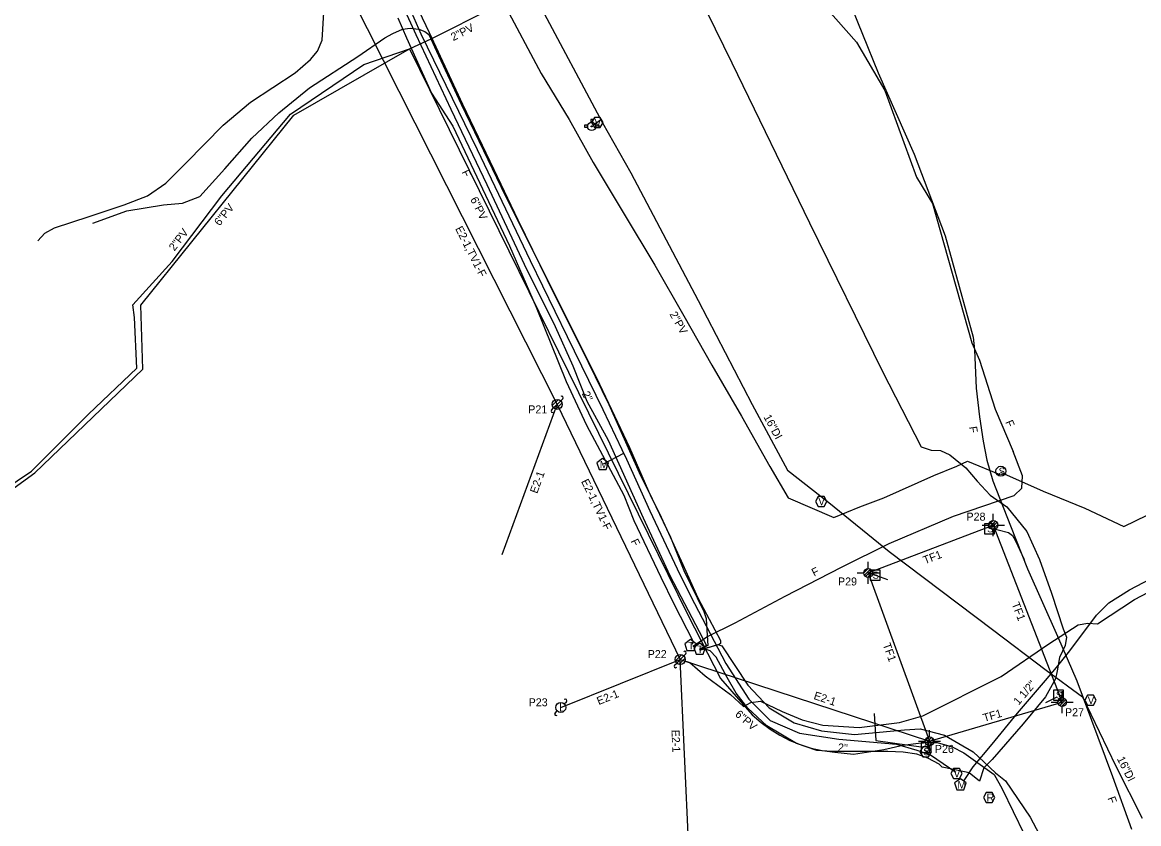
# Model space of a CAD drawing. Extents: x 1741604 to 1825760, y 1164229 to 1194908.
# Drawn here: x 1755344 to 1755902, y 1168344 to 1168745 of the extents above; entities that cross this region are included whole.
import ezdxf

# ---------------------------------------------------------------- set-up
doc = ezdxf.new("R2010")
doc.units = 0
for name, color, linetype in [('RD_EX_SU_Elec', 7, 'Continuous'), ('RD_EX_SU_H2O', 7, 'Continuous'), ('RD_EX_SU_Ovhd', 7, 'Continuous'), ('RD_EX_SU_Pole', 7, 'Continuous'), ('RD_EX_SU_Sewer', 7, 'Continuous'), ('RD_EX_SU_Telecom', 7, 'Continuous'), ('RD_EX_SU_Trfc', 7, 'Continuous'), ('RD_EX_SU_TX_H2O', 7, 'Continuous'), ('RD_EX_SU_TX_Pole', 7, 'Continuous'), ('RD_EX_SU_TX_Sewer', 7, 'Continuous'), ('RD_EX_SU_TX_Telecom', 7, 'Continuous')]:
    doc.layers.add(name, color=color, linetype=linetype)

# ---------------------------------------------------------------- blocks, each defined once
blk = doc.blocks.new('SUE_SMH')
at = {"layer": 'RD_EX_SU_Sewer'}
blk.add_circle((0, 0), 2.5, dxfattribs=at)
blk.add_text('S', height=3.57, dxfattribs=at).set_placement((-1.1, -1.79))

msp = doc.modelspace()

# ---------------------------------------------------------------- linework, layer by layer
at = {"layer": 'RD_EX_SU_Elec'}
msp.add_lwpolyline([(1755352.15, 1168636.03), (1755355.71, 1168639.76), (1755360.62, 1168642.49), (1755377.96, 1168648.25), (1755395.32, 1168654.04), (1755407.08, 1168658.47), (1755416.27, 1168664.85), (1755426.19, 1168674.91), (1755444.85, 1168693.91), (1755458.49, 1168705.44), (1755480.84, 1168720.11), (1755488.48, 1168726.7), (1755492.01, 1168730.8), (1755494.34, 1168736.34), (1755495.74, 1168758.73), (1755498.75, 1168776.84)], dxfattribs=at)
at = {"layer": 'RD_EX_SU_H2O'}
for p, q in [((1755627.04, 1168693.86), (1755625.4, 1168693.86)), ((1755625.4, 1168693.86), (1755625.4, 1168692.81)), ((1755625.4, 1168692.81), (1755627, 1168692.81)), ((1755628.57, 1168696.63), (1755628.57, 1168695.3)), ((1755629.62, 1168696.63), (1755628.57, 1168696.63)), ((1755629.62, 1168695.27), (1755629.62, 1168696.63)), ((1755629.84, 1168693.84), (1755633.69, 1168696.62)), ((1755632.75, 1168693.86), (1755631.06, 1168693.86)), ((1755631.1, 1168692.81), (1755632.75, 1168692.81)), ((1755632.75, 1168692.81), (1755632.75, 1168693.86)), ((1755635.04, 1168524.51), (1755645.11, 1168529.78))]:
    msp.add_line(p, q, dxfattribs=at)
for points in [[(1755385.42, 1169098.44), (1755401.32, 1169066.46), (1755415.89, 1169036.4), (1755422.95, 1169020.76), (1755426.26, 1169009.34), (1755463.14, 1168972.48), (1755499.82, 1168933.69), (1755512.6, 1168909), (1755538.91, 1168856.4), (1755564.45, 1168803.54), (1755584.77, 1168764.26), (1755602.59, 1168754.78), (1755634.52, 1168695.09), (1755648.65, 1168669.94), (1755682.22, 1168606.15), (1755709.26, 1168554.06), (1755726.87, 1168521.3)], [(1755537.79, 1168752.87), (1755543.72, 1168739.55), (1755571.82, 1168681.62), (1755598.4, 1168626.16), (1755616.79, 1168588.07), (1755634.63, 1168551.68), (1755644.21, 1168531.62), (1755646.53, 1168526.85), (1755658.08, 1168500.86), (1755671.83, 1168471.89), (1755678.5, 1168458.37), (1755696.16, 1168424.57), (1755707.62, 1168406.78), (1755718.29, 1168395.98), (1755732.94, 1168389.76), (1755752.68, 1168386.64), (1755781.36, 1168384.25), (1755791.61, 1168381.24), (1755798.5, 1168378.79), (1755811.16, 1168370.13)], [(1755726.87, 1168521.3), (1755747.63, 1168505.06), (1755777.82, 1168480.62), (1755829.49, 1168441.52), (1755856.27, 1168421.17), (1755874.43, 1168407.88), (1755891.14, 1168373.18), (1755904.2, 1168347.14)], [(1755815.25, 1168366.07), (1755819.84, 1168372.8), (1755829.29, 1168384.27), (1755841.99, 1168399.77), (1755855.87, 1168416.06), (1755861.36, 1168422.49), (1755868.12, 1168430.87), (1755881.49, 1168448.74), (1755887.6, 1168454.86), (1755897.94, 1168461.44), (1755918.53, 1168472.25)]]:
    msp.add_lwpolyline(points, dxfattribs=at)
for points in [[(1755634.81, 1168695.15), (1755633.37, 1168697.65), (1755630.48, 1168697.65), (1755629.04, 1168695.15), (1755630.48, 1168692.65), (1755633.37, 1168692.65)], [(1755634.55, 1168527.07), (1755631.64, 1168524.96), (1755632.75, 1168521.55), (1755636.34, 1168521.55), (1755637.45, 1168524.96)], [(1755746.64, 1168505.62), (1755745.2, 1168508.12), (1755742.31, 1168508.12), (1755740.87, 1168505.62), (1755742.31, 1168503.12), (1755745.2, 1168503.12)], [(1755881.31, 1168406.21), (1755879.87, 1168408.71), (1755876.98, 1168408.71), (1755875.54, 1168406.21), (1755876.98, 1168403.71), (1755879.87, 1168403.71)], [(1755814.29, 1168369.49), (1755812.85, 1168371.99), (1755809.96, 1168371.99), (1755808.52, 1168369.49), (1755809.96, 1168366.99), (1755812.85, 1168366.99)], [(1755813.37, 1168366.89), (1755810.46, 1168364.79), (1755811.57, 1168361.38), (1755815.16, 1168361.38), (1755816.27, 1168364.79)]]:
    msp.add_lwpolyline(points, close=True, dxfattribs=at)
for radius in [2.1, 0.263]:
    msp.add_circle((1755629.05, 1168693.25), radius, dxfattribs=at)
for start, end in [(163.3387, 192.315), (74.2455, 103.2128), (347.685, 16.6613)]:
    msp.add_arc((1755629.05, 1168693.25), 2.1, start, end, dxfattribs=at)
at = {"layer": 'RD_EX_SU_Ovhd'}
for p, q in [((1755499.08, 1168777.54), (1755611.8, 1168554.19)), ((1755584.39, 1168479.07), (1755611.8, 1168554.19)), ((1755611.8, 1168554.19), (1755673.33, 1168426.55)), ((1755767.32, 1168469.86), (1755829.82, 1168493.82)), ((1755829.82, 1168493.82), (1755864.24, 1168405.22)), ((1755767.32, 1168469.86), (1755797.9, 1168385.65)), ((1755613.6, 1168402.59), (1755673.33, 1168426.55)), ((1755678.06, 1168323.63), (1755673.33, 1168426.55)), ((1755673.33, 1168426.55), (1755797.9, 1168385.65)), ((1755797.9, 1168385.65), (1755864.24, 1168405.22))]:
    msp.add_line(p, q, dxfattribs=at)
at = {"layer": 'RD_EX_SU_Pole'}
for p, q in [((1755609.38, 1168553.54), (1755612.45, 1168556.6)), ((1755610.03, 1168552.42), (1755613.57, 1168555.95)), ((1755611.15, 1168551.77), (1755614.21, 1168554.83)), ((1755613.57, 1168555.95), (1755614.63, 1168557.01)), ((1755608.97, 1168551.36), (1755610.03, 1168552.42)), ((1755829.82, 1168496.04), (1755829.82, 1168499.35)), ((1755824.3, 1168493.82), (1755827.6, 1168493.82)), ((1755827.61, 1168493.96), (1755829.69, 1168496.04)), ((1755827.86, 1168492.8), (1755830.85, 1168495.78)), ((1755828.51, 1168492.04), (1755831.61, 1168495.13)), ((1755829.52, 1168491.63), (1755832.02, 1168494.12)), ((1755829.82, 1168488.3), (1755829.82, 1168491.61)), ((1755832.04, 1168493.82), (1755835.34, 1168493.82)), ((1755767.32, 1168472.08), (1755767.32, 1168475.39)), ((1755761.8, 1168469.86), (1755765.11, 1168469.86)), ((1755765.11, 1168469.99), (1755767.2, 1168472.07)), ((1755765.36, 1168468.83), (1755768.36, 1168471.82)), ((1755766.01, 1168468.07), (1755769.12, 1168471.16)), ((1755767.02, 1168467.66), (1755769.52, 1168470.15)), ((1755769.54, 1168469.86), (1755772.85, 1168469.86)), ((1755767.32, 1168464.33), (1755767.32, 1168467.64)), ((1755670.5, 1168423.73), (1755671.56, 1168424.79)), ((1755670.91, 1168425.91), (1755673.98, 1168428.97)), ((1755671.56, 1168424.79), (1755675.1, 1168428.32)), ((1755672.68, 1168424.14), (1755675.74, 1168427.2)), ((1755675.1, 1168428.32), (1755676.16, 1168429.38)), ((1755864.24, 1168407.44), (1755864.24, 1168410.75)), ((1755615.37, 1168404.35), (1755616.43, 1168405.42)), ((1755858.72, 1168405.22), (1755862.03, 1168405.22)), ((1755862.03, 1168405.35), (1755864.12, 1168407.43)), ((1755862.28, 1168404.19), (1755865.28, 1168407.18)), ((1755862.93, 1168403.43), (1755866.04, 1168406.52)), ((1755863.94, 1168403.02), (1755866.44, 1168405.51)), ((1755864.24, 1168399.69), (1755864.24, 1168403)), ((1755866.46, 1168405.22), (1755869.77, 1168405.22)), ((1755610.77, 1168399.76), (1755611.83, 1168400.82)), ((1755797.9, 1168387.87), (1755797.9, 1168391.18)), ((1755792.38, 1168385.65), (1755795.68, 1168385.65)), ((1755795.69, 1168385.78), (1755797.77, 1168387.86)), ((1755795.94, 1168384.62), (1755798.93, 1168387.61)), ((1755796.59, 1168383.86), (1755799.69, 1168386.95)), ((1755797.6, 1168383.45), (1755800.1, 1168385.94)), ((1755800.12, 1168385.65), (1755803.42, 1168385.65)), ((1755797.9, 1168380.12), (1755797.9, 1168383.43))]:
    msp.add_line(p, q, dxfattribs=at)
for centre, radius in [((1755611.8, 1168554.19), 2.5), ((1755829.82, 1168493.82), 2.22), ((1755767.32, 1168469.86), 2.22), ((1755673.33, 1168426.55), 2.5), ((1755613.6, 1168402.59), 2.5), ((1755864.24, 1168405.22), 2.22), ((1755797.9, 1168385.65), 2.22)]:
    msp.add_circle(centre, radius, dxfattribs=at)
for centre, start, end in [((1755614.1, 1168557.54), 315, 135), ((1755609.5, 1168550.83), 135, 315), ((1755675.63, 1168429.91), 315, 135), ((1755671.03, 1168423.2), 135, 315), ((1755615.9, 1168405.95), 315, 135), ((1755611.3, 1168399.23), 135, 315)]:
    msp.add_arc(centre, 0.75, start, end, dxfattribs=at)
at = {"layer": 'RD_EX_SU_Sewer'}
for p, q in [((1755480.23, 1168698.92), (1755538.02, 1168731.98)), ((1755403.78, 1168603.87), (1755480.23, 1168698.92)), ((1755404.72, 1168571.84), (1755403.78, 1168603.87))]:
    msp.add_line(p, q, dxfattribs=at)
for points in [[(1755584.91, 1168755.1), (1755603.82, 1168719.72), (1755617.74, 1168696.64), (1755629.86, 1168675.11), (1755645.29, 1168649.26), (1755660.6, 1168623.75), (1755675.18, 1168598.54), (1755689.17, 1168573.75), (1755703.97, 1168548.28), (1755718.09, 1168523.12), (1755727.27, 1168507.43), (1755750.04, 1168497.58), (1755763.04, 1168502.91), (1755775.14, 1168507.49), (1755800.07, 1168518.6), (1755811.62, 1168523.3), (1755816.99, 1168525.81), (1755833.04, 1168519.03)], [(1755283.97, 1168476.99), (1755349.04, 1168520.82), (1755377.51, 1168549.27), (1755401.74, 1168572.3), (1755400.52, 1168597.56), (1755399.65, 1168604.04), (1755419.32, 1168625.72), (1755444.21, 1168658.58), (1755478.45, 1168699.38), (1755515.21, 1168724.24), (1755538.02, 1168731.98), (1755549.18, 1168737.18), (1755579.59, 1168752.57)], [(1755538.02, 1168731.98), (1755677.08, 1168448.83), (1755693.42, 1168417.12), (1755709.32, 1168398.86), (1755713.78, 1168394.98), (1755718.32, 1168391.64), (1755723.12, 1168388.68), (1755728.15, 1168386.12), (1755733.36, 1168383.98), (1755738.74, 1168382.28), (1755744.23, 1168381.02), (1755750.62, 1168380.15), (1755759.98, 1168379.15), (1755775.13, 1168381.6), (1755784.54, 1168383.67), (1755792.42, 1168384.71), (1755797.45, 1168385.03), (1755801.74, 1168384.97), (1755809.29, 1168382.85), (1755815.1, 1168379.89), (1755830.27, 1168368.97), (1755834.26, 1168361.92), (1755845.18, 1168339.2)], [(1755833.4, 1168520.19), (1755854.68, 1168510.84), (1755875.52, 1168502.34), (1755895.06, 1168493.1), (1755930.11, 1168510.09), (1755971.34, 1168530.46), (1756049.09, 1168567.75), (1756167.6, 1168625.42), (1756207.81, 1168645.15), (1756226.79, 1168655.14), (1756237.27, 1168663.29), (1756249.83, 1168676.69), (1756258.66, 1168686.07), (1756260.41, 1168686.42), (1756288.47, 1168691.24), (1756293.05, 1168692.1), (1756294.39, 1168670.91), (1756296.55, 1168641.01), (1756298.7, 1168612.4), (1756300.63, 1168584.8), (1756304.07, 1168543.33), (1756307.31, 1168500.11), (1756311.13, 1168456.78)], [(1755174.41, 1168387.89), (1755210.34, 1168414.64), (1755245.09, 1168435.23), (1755286.99, 1168473.67), (1755350.64, 1168519.87), (1755404.72, 1168571.84)]]:
    msp.add_lwpolyline(points, dxfattribs=at)
msp.add_lwpolyline([(1755830.66, 1168357.52), (1755829.22, 1168360.02), (1755826.33, 1168360.02), (1755824.88, 1168357.52), (1755826.33, 1168355.02), (1755829.22, 1168355.02)], close=True, dxfattribs=at)
at = {"layer": 'RD_EX_SU_Telecom'}
for points in [[(1755590.16, 1169126.29), (1755590.98, 1169107.71), (1755588.59, 1169093.98), (1755585.74, 1169086.47), (1755598.29, 1169061.2), (1755650.69, 1168954.78), (1755669.04, 1168919.98), (1755680.52, 1168896.3), (1755696.94, 1168870.9), (1755720.15, 1168844.14), (1755735.51, 1168794.5), (1755736.19, 1168774.57), (1755740.79, 1168758.88), (1755761.5, 1168735.33), (1755775.66, 1168711.24), (1755791.36, 1168667.81), (1755799.39, 1168654.61), (1755819.15, 1168584.91), (1755822.92, 1168576.29), (1755830.76, 1168551.82), (1755839.8, 1168530.61)], [(1755643.16, 1168988.99), (1755650.24, 1168970.42), (1755659.27, 1168949.97), (1755675.7, 1168921.3), (1755696.74, 1168888.73), (1755711.98, 1168863.4), (1755726.14, 1168838.3), (1755741.49, 1168798.28), (1755756.63, 1168758.91), (1755772.29, 1168720.09), (1755790.19, 1168679.27), (1755805.71, 1168638.46), (1755819.76, 1168587.82), (1755820.42, 1168581.52)], [(1755657.46, 1168810.23), (1755699.13, 1168725.09), (1755737.87, 1168644.92), (1755774.46, 1168570.64), (1755793.8, 1168532.87), (1755798.73, 1168531.24), (1755803.48, 1168531.11), (1755808.03, 1168529.01), (1755816.1, 1168522.43), (1755821.75, 1168515.75), (1755828.3, 1168508.82), (1755836.59, 1168502.92), (1755846.59, 1168490.64), (1755852.89, 1168476.58), (1755858.89, 1168459.81), (1755864.75, 1168441.96), (1755866.44, 1168437.76), (1755865.72, 1168433.54), (1755862.91, 1168427.6), (1755861.7, 1168420.97), (1755860.93, 1168416.93), (1755855.87, 1168407.81), (1755844.79, 1168394.37), (1755829.28, 1168376.59), (1755825.07, 1168372.41), (1755822.91, 1168365.68), (1755817.74, 1168369.85), (1755809.06, 1168371.75), (1755804.23, 1168372.69), (1755802.82, 1168374.22), (1755797.14, 1168377.22), (1755791.58, 1168379.14), (1755784.84, 1168380.17), (1755777.16, 1168380.53), (1755749.1, 1168380.46), (1755741.68, 1168381.1), (1755731.52, 1168384.53), (1755716.59, 1168393.46), (1755707.1, 1168402.22), (1755701.25, 1168409.7), (1755696.77, 1168417.52), (1755691.3, 1168427.8), (1755688.36, 1168430.83), (1755685.79, 1168431.67), (1755683.46, 1168431.17)], [(1755529.29, 1168765.17), (1755541.09, 1168739.22), (1755558.67, 1168701.88), (1755576.72, 1168664.11), (1755595.28, 1168624.37), (1755610.86, 1168593.19), (1755619.66, 1168573.4), (1755626.6, 1168555.82), (1755637.26, 1168536.36), (1755654.8, 1168497.45), (1755668.14, 1168468.66), (1755686.47, 1168433.56), (1755682.82, 1168431.61)], [(1755533.94, 1168769.38), (1755547.81, 1168740.19), (1755564.48, 1168704.4), (1755580.18, 1168671.75), (1755592.08, 1168646.44), (1755610.47, 1168608.91), (1755627.34, 1168575.22), (1755637.64, 1168554.12), (1755652.77, 1168520.08), (1755663.73, 1168497.74), (1755674.59, 1168474.03), (1755682.07, 1168457.47), (1755693.44, 1168436.04), (1755693.38, 1168434.49), (1755692.39, 1168433.88), (1755683.15, 1168431.4)], [(1755532.15, 1168747.5), (1755536.58, 1168737.5), (1755549.01, 1168709.89), (1755559.7, 1168693.42), (1755588.06, 1168633.45), (1755601.28, 1168602.82), (1755616.31, 1168565.61), (1755626.54, 1168543.8), (1755645.11, 1168508.8), (1755650.21, 1168496.11), (1755663.64, 1168467.83), (1755670.15, 1168454.35), (1755679.81, 1168435.61), (1755679.25, 1168434)], [(1755512.1, 1168728.24), (1755525.71, 1168737.52), (1755529.7, 1168739.68), (1755534.51, 1168741.84), (1755538.4, 1168742.46), (1755542.64, 1168741.85), (1755545.72, 1168740.78), (1755547.74, 1168739.27), (1755552.53, 1168728.77), (1755563.81, 1168704.31), (1755586.05, 1168658.34), (1755599.42, 1168631.31), (1755616.67, 1168597.14), (1755633.05, 1168564.37), (1755647.91, 1168532.61), (1755657.47, 1168510.73), (1755668.47, 1168487.78), (1755675.2, 1168471.07), (1755685.09, 1168450.55), (1755686.31, 1168447), (1755686.46, 1168443.88), (1755687.07, 1168433.57), (1755682.96, 1168431.41)], [(1755379.76, 1168644.85), (1755396.66, 1168651.06), (1755415.05, 1168653.92), (1755424.6, 1168654.88), (1755433.24, 1168658.21), (1755445.63, 1168671.96), (1755459.2, 1168687.37), (1755472.73, 1168700.1), (1755487.98, 1168712.53), (1755512.1, 1168728.24)], [(1755820.42, 1168581.52), (1755821.25, 1168562.36), (1755823, 1168547.9), (1755824.82, 1168535.83), (1755826.58, 1168526.22), (1755829.64, 1168515.94), (1755838.44, 1168493.5), (1755846.87, 1168471.86), (1755861.95, 1168438.23), (1755871.65, 1168415.93), (1755889.34, 1168367.97), (1755898.9, 1168341.72)], [(1755679.58, 1168433.3), (1755687.03, 1168438.08), (1755700.87, 1168444.86), (1755725.73, 1168458.23), (1755753.87, 1168472.69), (1755777.85, 1168484.62), (1755809.97, 1168498.23), (1755840.19, 1168508.58), (1755844.04, 1168512.33), (1755844.37, 1168518.5), (1755839.8, 1168530.61)], [(1755674.42, 1168426.23), (1755678.17, 1168425.12), (1755685.87, 1168418.31), (1755698.42, 1168409.03), (1755704.98, 1168403.09), (1755708.6, 1168405.04), (1755713.44, 1168405.79), (1755724.28, 1168400.63), (1755734.34, 1168396.34), (1755744.65, 1168393.75), (1755762.76, 1168392.58), (1755782.9, 1168395.04), (1755794.58, 1168398.36), (1755833.79, 1168418), (1755857.65, 1168434.43), (1755872.17, 1168443.94), (1755877.09, 1168444.69), (1755881.84, 1168444.33), (1755900.35, 1168456.59), (1755937.92, 1168476.33)], [(1755683.09, 1168431.31), (1755692.17, 1168434), (1755694.1, 1168433.4), (1755707.11, 1168413.71), (1755717.73, 1168402.31), (1755730.31, 1168394.95), (1755743.9, 1168390.86), (1755760.42, 1168389), (1755785.37, 1168391.33), (1755793.2, 1168391.88), (1755805.48, 1168388.79), (1755819.73, 1168380.45), (1755830.93, 1168369.82), (1755835.84, 1168365.8), (1755848.29, 1168347.64), (1755863.29, 1168319.35), (1755867.59, 1168310.21)]]:
    msp.add_lwpolyline(points, dxfattribs=at)
for points in [[(1755678.47, 1168436.5), (1755675.62, 1168434.42), (1755676.71, 1168431.07), (1755680.24, 1168431.07), (1755681.33, 1168434.42)], [(1755683.05, 1168434.65), (1755680.19, 1168432.57), (1755681.28, 1168429.22), (1755684.81, 1168429.22), (1755685.9, 1168432.57)]]:
    msp.add_lwpolyline(points, close=True, dxfattribs=at)
at = {"layer": 'RD_EX_SU_Trfc'}
for p, q in [((1755829.87, 1168493.72), (1755828.09, 1168492.81)), ((1755861.54, 1168407.8), (1755855.92, 1168404.89)), ((1755864.26, 1168405.59), (1755862.85, 1168408.31)), ((1755797.33, 1168383.16), (1755797.76, 1168385.17))]:
    msp.add_line(p, q, dxfattribs=at)
for points in [[(1755830.41, 1168494.45), (1755825.41, 1168494.45), (1755825.41, 1168489.45), (1755830.41, 1168489.45)], [(1755773.19, 1168471.27), (1755768.2, 1168471.27), (1755768.2, 1168466.27), (1755773.19, 1168466.27)], [(1755864.85, 1168411.29), (1755859.85, 1168411.29), (1755859.85, 1168406.29), (1755864.85, 1168406.29)], [(1755798.91, 1168380.45), (1755797.47, 1168382.95), (1755794.58, 1168382.95), (1755793.14, 1168380.45), (1755794.58, 1168377.95), (1755797.47, 1168377.95)], [(1755798.83, 1168384.96), (1755793.83, 1168384.96), (1755793.83, 1168379.96), (1755798.83, 1168379.96)]]:
    msp.add_lwpolyline(points, close=True, dxfattribs=at)
for points in [[(1755828.57, 1168492.19), (1755832.25, 1168491.47), (1755837.41, 1168490.1), (1755839.43, 1168488.53), (1755841, 1168485.91), (1755845.32, 1168476.65)], [(1755767.53, 1168469.73), (1755771.36, 1168468.58), (1755776.92, 1168466.63)], [(1755770.34, 1168399.61), (1755771.12, 1168385.96), (1755794.96, 1168382.77)]]:
    msp.add_lwpolyline(points, dxfattribs=at)

# ---------------------------------------------------------------- block references
at = {"layer": 'RD_EX_SU_Sewer'}
msp.add_blockref('SUE_SMH', (1755833.61, 1168520.73), dxfattribs=at)

# ---------------------------------------------------------------- texts
at = {"layer": 'RD_EX_SU_H2O'}
for s, p in [('V', (1755630.49, 1168693.28)), ('M', (1755633.11, 1168522.15)), ('V', (1755742.32, 1168503.75)), ('V', (1755876.99, 1168404.33)), ('V', (1755809.97, 1168367.61)), ('M', (1755811.93, 1168361.97))]:
    msp.add_text(s, height=3.75, dxfattribs=at).set_placement(p)
at = {"layer": 'RD_EX_SU_Ovhd'}
for s, rotation, p in [('E2-1,TV1-F', 296.7794, (1755560.72, 1168642.09)), ('E2-1', 69.955, (1755601.8, 1168509.29)), ('E2-1,TV1-F', 295.7388, (1755623.7, 1168515.68)), ('TF1', 20.9796, (1755795.66, 1168474.18)), ('TF1', 291.2317, (1755838.91, 1168454.39)), ('TF1', 289.9557, (1755774.5, 1168434.02)), ('E2-1', 21.865, (1755632.57, 1168403.73)), ('E2-1', 341.8207, (1755739.73, 1168406.85)), ('TF1', 16.435, (1755825.35, 1168395.32)), ('E2-1', 272.63, (1755668.94, 1168391.32))]:
    msp.add_text(s, height=4, rotation=rotation, dxfattribs=at).set_placement(p)
at = {"layer": 'RD_EX_SU_Pole'}
msp.add_text('L', height=4, dxfattribs=at).set_placement((1755612.74, 1168400.59))
at = {"layer": 'RD_EX_SU_Sewer'}
msp.add_text('R', height=4, dxfattribs=at).set_placement((1755826.43, 1168355.52))
at = {"layer": 'RD_EX_SU_Telecom'}
for p in [(1755677.22, 1168431.62), (1755681.79, 1168429.77)]:
    msp.add_text('T', height=3.75, dxfattribs=at).set_placement(p)
at = {"layer": 'RD_EX_SU_Trfc'}
for p in [(1755826.73, 1168490.18), (1755769.51, 1168467), (1755861.16, 1168407.02), (1755794.84, 1168378.68), (1755795.15, 1168380.7)]:
    msp.add_text('S', height=3.53, dxfattribs=at).set_placement(p)
at = {"layer": 'RD_EX_SU_TX_H2O'}
for s, rotation, p in [('2"', 296.1172, (1755624.06, 1168559.61)), ('16"DI', 298.2548, (1755714.87, 1168547.86)), ('1 1/2"', 49.5575, (1755842.5, 1168403.45)), ('2"', 355.2555, (1755752, 1168380.67)), ('16"DI', 296.6423, (1755891.51, 1168376.89))]:
    msp.add_text(s, height=4, rotation=rotation, dxfattribs=at).set_placement(p)
at = {"layer": 'RD_EX_SU_TX_Pole'}
for s, p in [('P21', (1755597.37, 1168549.68)), ('P28', (1755816.4, 1168496.03)), ('P29', (1755752.18, 1168463.6)), ('P22', (1755657.05, 1168427.28)), ('P23', (1755597.55, 1168403.16)), ('P27', (1755865.66, 1168398.19)), ('P26', (1755800.6, 1168379.84))]:
    msp.add_text(s, height=4, dxfattribs=at).set_placement(p)
at = {"layer": 'RD_EX_SU_TX_Sewer'}
for s, rotation, p in [('2"PV', 26.8559, (1755559.9, 1168735.88)), ('6"PV', 51.1862, (1755443.09, 1168643.18)), ('6"PV', 296.156, (1755568.25, 1168656.8)), ('2"PV', 52.858, (1755420.52, 1168630.62)), ('2"PV', 299.4314, (1755667.86, 1168599.31)), ('6"PV', 318.9697, (1755700.44, 1168398.63))]:
    msp.add_text(s, height=4, rotation=rotation, dxfattribs=at).set_placement(p)
at = {"layer": 'RD_EX_SU_TX_Telecom'}
for rotation, p in [(295.3092, (1755563.95, 1168670.39)), (278.5731, (1755817.69, 1168542.91)), (293.0865, (1755835.7, 1168545.33)), (295.4034, (1755648.47, 1168485.79)), (27.2124, (1755740.28, 1168467.96)), (289.9985, (1755886.87, 1168357.21))]:
    msp.add_text('F', height=4, rotation=rotation, dxfattribs=at).set_placement(p)

doc.saveas('drawing.dxf')
